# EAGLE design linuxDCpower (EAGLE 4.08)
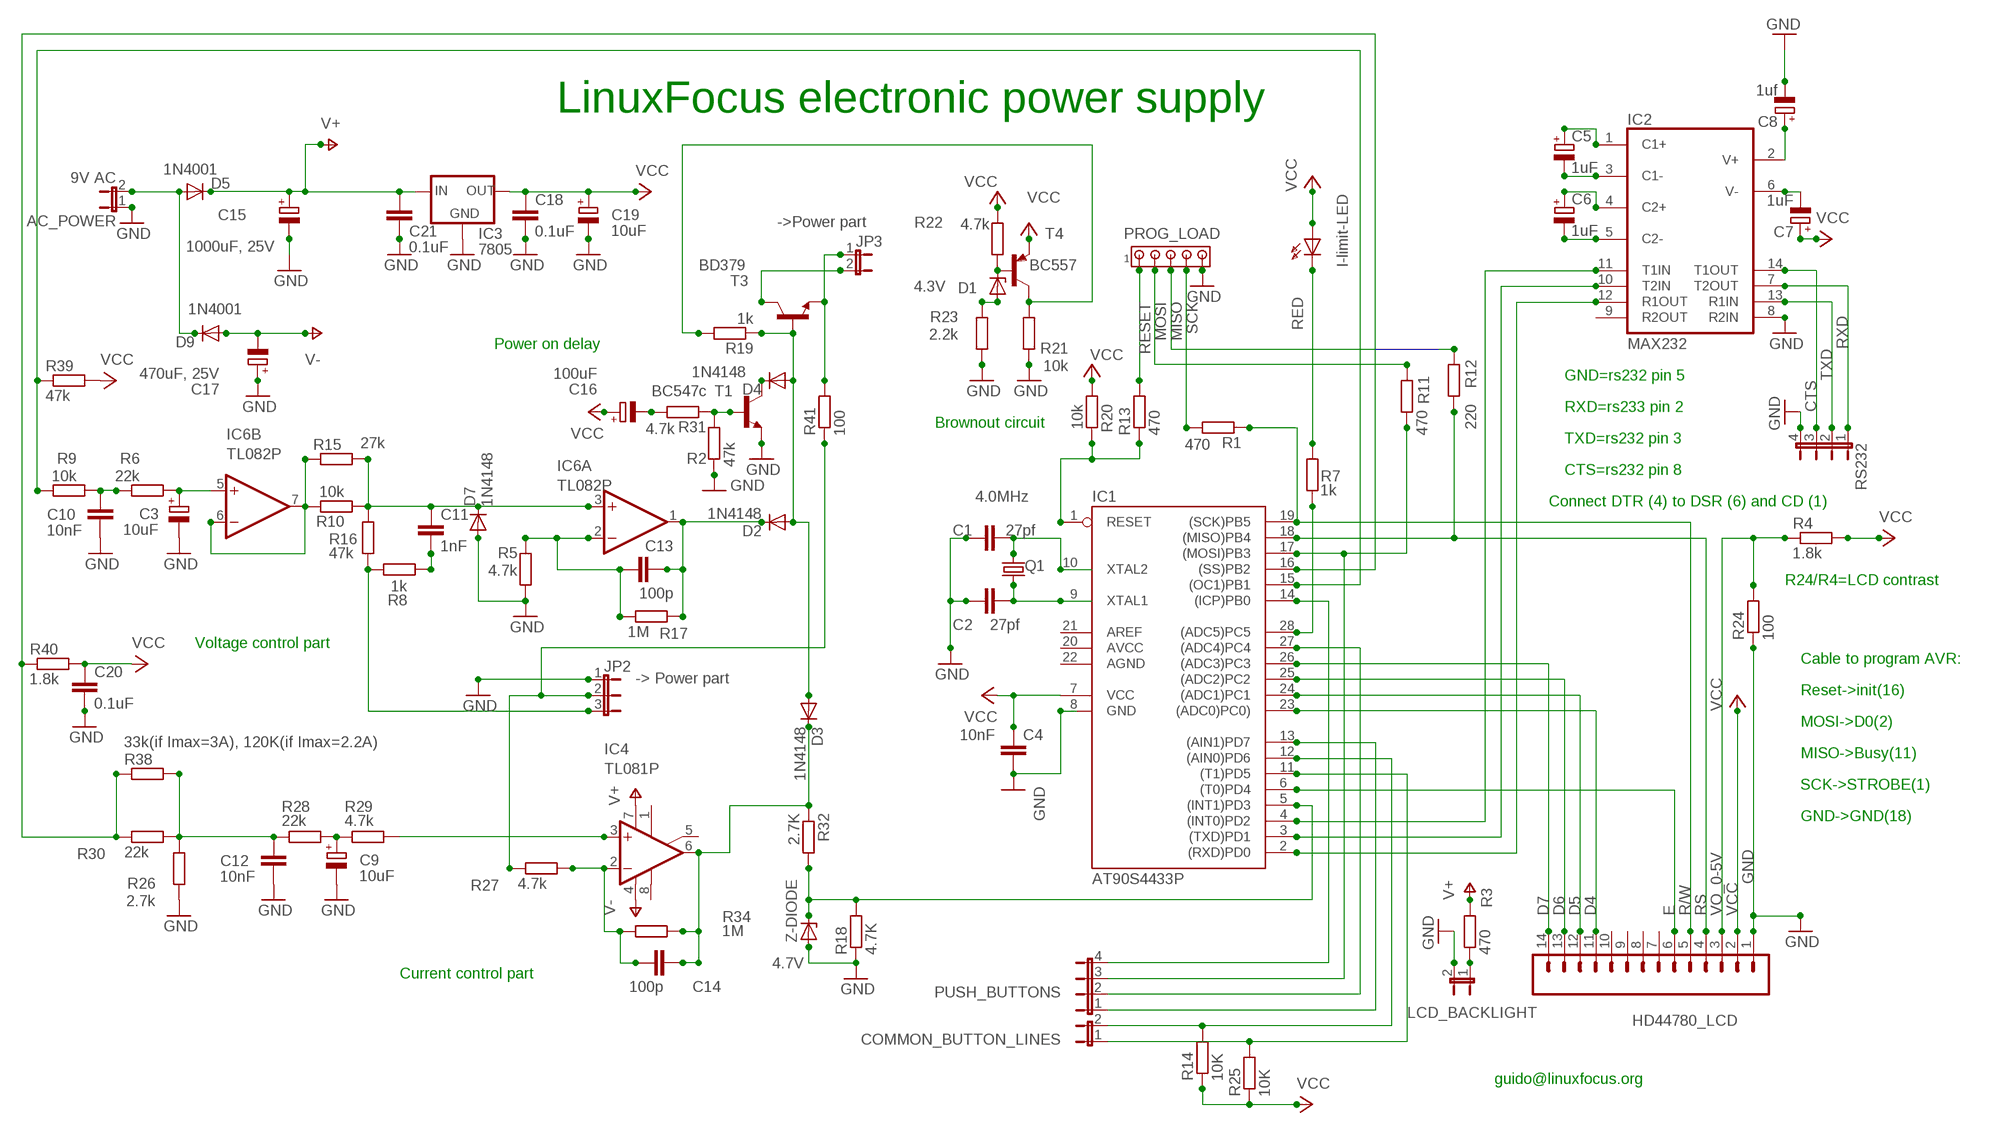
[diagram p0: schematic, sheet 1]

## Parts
AC_POWER  9V AC  JP1E  [JP1]
C1  27pf  C2.5/2  [C2.5-2]
C2  27pf  C2.5/2  [C2.5-2]
C3  10uF  CPOL-EUE2.5-6  [E2,5-6]
C4  10nF  C-EU025-030X050  [C025-030X050]
C5  1uF  CPOL-EUE2.5-6  [E2,5-6]
C6  1uF  CPOL-EUE2.5-6  [E2,5-6]
C7  1uF  CPOL-EUE2.5-6  [E2,5-6]
C8  1uf  CPOL-EUE2.5-6  [E2,5-6]
C9  10uF  CPOL-EUE2.5-6  [E2,5-6]
C10  10nF  C-EU025-030X050  [C025-030X050]
C11  1nF  C-EU025-030X050  [C025-030X050]
C12  10nF  C-EU025-030X050  [C025-030X050]
C13  100p  C-EU025-030X050  [C025-030X050]
C14  100p  C-EU025-030X050  [C025-030X050]
C15  1000uF, 25V  CPOL-EUE5-13  [E5-13]
C16  100uF  CPOL-EUE2.5-6  [E2,5-6]
C17  470uF, 25V  CPOL-EUE3.5-10  [E3,5-10]
C18  0.1uF  C-EU025-040X050  [C025-040X050]
C19  10uF  CPOL-EUE2.5-7  [E2,5-7]
C20  0.1uF  C-EU025-030X050  [C025-030X050]
C21  0.1uF  C-EU025-030X050  [C025-030X050]
COMMON_BUTTON_LINES  JP1E  [JP1]
D1  4.3V  ZENER-DIODEZD-5  [ZDIO-5]
D2  1N4148  DIODE-D-5  [D-5]
D3  1N4148  DIODE-D-5  [D-5]
D4  1N4148  DIODE-D-5  [D-5]
D5  1N4001  1N4004  [DO41-10]
D7  1N4148  DIODE-D-5  [D-5]
D9  1N4001  1N4004  [DO41-10]
HD44780_LCD  M14  [14P]
IC1  AT90S4433P  [DIL28-3]
IC2  MAX232  [DIL16]
IC3  7805  78XXS  [78XXS]
IC4  TL081P  [DIL08]
IC6  TL082P  [DIL08]
JP2  -> Power part  JP2E  [JP2]
JP3  ->Power part  JP1E  [JP1]
LCD_BACKLIGHT  JP1E  [JP1]
PROG_LOAD  MTA05-100  [10X05MTA]
PUSH_BUTTONS  JP4E  [JP4]
Q1  4.0MHz  HC49U-V  [HC49U-V]
R1  470  R-EU_0204/7  [0204/7]
R2  47k  R-EU_0204/7  [0204/7]
R3  470  R-EU_0204/5  [0204/5]
R4  1.8k  R-EU_0204/7  [0204/7]
R5  4.7k  R-EU_0204/5  [0204/5]
R6  22k  R-EU_0204/5  [0204/5]
R7  1k  R-EU_0204/7  [0204/7]
R8  1k  R-EU_0204/7  [0204/7]
R9  10k  R-EU_0204/7  [0204/7]
R10  10k  R-EU_0204/7  [0204/7]
R11  470  R-EU_0207/10  [0207/10]
R12  220  R-EU_0207/10  [0207/10]
R13  470  R-EU_0204/7  [0204/7]
R14  10K  R-EU_0207/10  [0207/10]
R15  27k  R-EU_0204/7  [0204/7]
R16  47k  R-EU_0204/7  [0204/7]
R17  1M  R-EU_0204/5  [0204/5]
R18  4.7K  R-EU_0204/7  [0204/7]
R19  1k  R-EU_0204/7  [0204/7]
R20  10k  R-EU_0204/7  [0204/7]
R21  10k  R-EU_0204/7  [0204/7]
R22  4.7k  R-EU_0204/7  [0204/7]
R23  2.2k  R-EU_0204/7  [0204/7]
R24  100  R-EU_0204/7  [0204/7]
R25  10K  R-EU_0204/7  [0204/7]
R26  2.7k  R-EU_0204/7  [0204/7]
R27  4.7k  R-EU_0204/7  [0204/7]
R28  22k  R-EU_0204/7  [0204/7]
R29  4.7k  R-EU_0204/7  [0204/7]
R30  22k  R-EU_0204/7  [0204/7]
R31  4.7k  R-EU_0204/7  [0204/7]
R32  2.7K  R-EU_0204/7  [0204/7]
R34  1M  R-EU_0204/7  [0204/7]
R38  33k(if Imax=3A), 120K(if Imax=2.2A)  R-EU_0204/7  [0204/7]
R39  47k  R-EU_0204/7  [0204/7]
R40  1.8k  R-EU_0204/7  [0204/7]
R41  100  R-EU_0204/7  [0204/7]
RED  I-limit-LED  LED3MM  [LED3MM]
RS232  JP4E  [JP4]
T1  BC547c  BC547  [TO92]
T3  BD379  BD139  [TO126]
T4  BC557  [TO92]
Z-DIODE  4.7V  ZTE  [DO35Z10]

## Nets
CTS: IC2.14(T1OUT) RS232.3
D4: HD44780_LCD.11 IC1.23((ADC0)PC0))
D5: HD44780_LCD.12 IC1.24((ADC1)PC1)
D6: HD44780_LCD.13 IC1.25((ADC2)PC2)
D7: HD44780_LCD.14 IC1.26((ADC3)PC3)
E: HD44780_LCD.6 IC1.6((T0)PD4)
GND: AC_POWER.1 C1.1 C2.1 C3.- C4.2 C8.- C9.- C10.2 C12.2 C15.- C17.+ C18.2 C19.- C20.2 C21.2 D7.A HD44780_LCD.1 IC1.8(GND) IC2.8(R2IN) IC3.GND JP2.1 LCD_BACKLIGHT.2 PROG_LOAD.5 R2.1 R5.1 R18.1 R21.1 R23.1 R24.1 R26.1 RS232.4 T1.1(E) Z-DIODE.A
MISO: PROG_LOAD.3 R12.2
MOSI: PROG_LOAD.2 R11.2
N$1: IC1.17((MOSI)PB3) PUSH_BUTTONS.3 R11.1
N$2: C2.2 IC1.9(XTAL1) Q1.1
N$3: LCD_BACKLIGHT.1 R3.1
N$4: D2.A D3.A D4.A R19.1 T3.3(B)
N$5: IC1.28((ADC5)PC5) R7.2
N$6: D4.C T1.3(C)
N$7: R7.1 RED.K(C)
N$8: C13.2 D2.C IC6.1(A:OUT) R17.2
N$9: IC6.6(B:-IN) IC6.7(B:OUT) R10.2 R15.1
N$10: C13.1 IC6.2(A:-IN) R5.2 R17.1
N$11: C3.+ IC6.5(B:+IN) R6.1
N$12: C10.1 R6.2 R9.1
N$14: C14.2 IC4.2(-IN) R27.2 R34.1
N$15: C11.1 D7.C IC6.3(A:+IN) R10.1 R15.2 R16.1
N$16: C11.2 R8.1
N$17: AC_POWER.2 D5.A D9.C
N$18: IC1.16((SS)PB2) R30.1 R38.1 R40.1
N$19: IC1.14((ICP)PB0) PUSH_BUTTONS.4
N$20: IC1.13((AIN1)PD7) PUSH_BUTTONS.1
N$21: JP3.1 R41.2 T3.1(E)
N$24: IC1.1(RESET) R13.1 R20.2
N$25: C6.- IC2.5(C2-)
N$26: C6.+ IC2.4(C2+)
N$27: C7.- IC2.6(V-)
N$28: C8.+ IC2.2(V+)
N$29: C5.- IC2.3(C1-)
N$30: C5.+ IC2.1(C1+)
N$31: IC1.3((TXD)PD1) IC2.10(T2IN)
N$32: IC1.4((INT0)PD2) IC2.11(T1IN)
N$34: IC1.2((RXD)PD0) IC2.12(R1OUT)
N$36: C1.2 IC1.10(XTAL2) Q1.2
N$37: C9.+ R28.2 R29.1
N$38: C12.1 R26.2 R28.1 R30.2 R38.2
N$39: IC4.3(+IN) R29.2
N$40: IC1.15((OC1)PB1) R9.2 R39.1
N$41: C14.1 D3.C IC4.6(OUT) R32.1 R34.2
N$42: COMMON_BUTTON_LINES.2 IC1.12((AIN0)PD6) R14.2
N$43: JP3.2 T3.2(C)
N$44: R2.2 R31.1 T1.2(B)
N$45: COMMON_BUTTON_LINES.1 IC1.11((T1)PD5) R25.2
N$47: D1.A R23.2
N$48: D1.C R22.1 T4.2(B)
N$49: IC1.5((INT1)PD3) R18.2 R32.2 Z-DIODE.C
N$50: IC1.27((ADC4)PC4) PUSH_BUTTONS.2
N$51: C16.- R31.2
N$53: R19.2 R21.2 T4.3(C)
N$54: JP2.2 R27.1 R41.1
N$57: JP2.3 R8.2 R16.2
R/W: HD44780_LCD.5 IC1.19((SCK)PB5) R1.1
RESET: PROG_LOAD.1 R13.2
RS: HD44780_LCD.4 IC1.18((MISO)PB4) R12.1
RXD: IC2.7(T2OUT) RS232.1
SCK: PROG_LOAD.4 R1.2
TXD: IC2.13(R1IN) RS232.2
V+: C15.+ C21.1 D5.C IC3.IN IC4.7(V+) R3.2
V-: C17.- D9.A IC4.4(V-)
VCC: C4.1 C7.+ C16.+ C18.1 C19.+ C20.1 HD44780_LCD.2 IC1.7(VCC) IC3.OUT R4.2 R14.1 R20.1 R22.2 R25.1 R39.2 R40.2 RED.A T4.1(E)
VO_0-5V: HD44780_LCD.3 R4.1 R24.2
Unconnected: HD44780_LCD.7 HD44780_LCD.8 HD44780_LCD.9 HD44780_LCD.10 IC2.9(R2OUT) IC4.1(ON1) IC4.5(ON2) IC4.8(OPT)

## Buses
B$1

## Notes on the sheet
- LinuxFocus electronic power supply
- Power on delay
- GND=rs232 pin 5
- RXD=rs233 pin 2
- Brownout circuit
- TXD=rs232 pin 3
- CTS=rs232 pin 8
- Connect DTR (4) to DSR (6) and CD (1)
- R24/R4=LCD contrast
- Voltage control part
- Cable to program AVR:
- Reset->init(16)
- MOSI->D0(2)
- MISO->Busy(11)
- SCK->STROBE(1)
- GND->GND(18)
- Current control part
- guido@linuxfocus.org

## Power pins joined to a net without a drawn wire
AGND: IC1.22(AGND)
AREF: IC1.21(AREF)
AVCC: IC1.20(AVCC)
GND: IC2.15(GND)
V+: IC6.8(P:V+)
V-: IC6.4(P:V-)
VCC: IC2.16(VCC)

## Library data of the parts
AC_POWER COMMON_BUTTON_LINES JP3 LCD_BACKLIGHT = jumper:JP1E: JUMPER
C1 C2 = capacitor-wima:C: CAPACITOR
C3 C5-C9 C15-C17 C19 = rcl:CPOL-EU: POLARIZED CAPACITOR, European symbol
C4 C10-C14 C18 C20 C21 = rcl:C-EU: CAPACITOR, European symbol
D1 = diode:ZENER-DIODE: Z-Diode
D2-D4 D7 = diode:DIODE-: DIODE
D5 D9 = diode:1N4004: DIODE
HD44780_LCD = con-amp-quick:M14: AMP QUICK CONNECTOR
IC1 = atmel:AT90S4433: MICROCONTROLLER 4 Kbytes FLASH 128 bytes SRAM 256 bytes EEPROM UART 6-channel 10 bit ADC
IC2 = maxim:MAX232: RS232 TRANSEIVER
IC3 = v-reg:78XXS: VOLTAGE REGULATOR
IC4 = linear:TL081: OP AMP
IC6 = linear:TL082: OP AMP
JP2 = jumper:JP2E: JUMPER
PROG_LOAD = con-amp:MTA05-100: AMP CONNECTOR
PUSH_BUTTONS RS232 = jumper:JP4E: JUMPER
Q1 = crystal:HC49U-V: CRYSTAL
R1-R3 R5-R19 R24-R32 R34 R38-R41 = rcl:R-EU_: RESISTOR, European symbol
R4 R20-R23 = rcl_gus:R-EU_: RESISTOR, European symbol
RED = led:LED3MM: LED
T1 = transistor-npn:BC547: NPN TRANSISTOR
T3 = transistor-npn:BD139: NPN TRANSISTOR
T4 = transistor-pnp:BC557: PNP TRANSISTOR
Z-DIODE = diode:ZTE: Z DIODE

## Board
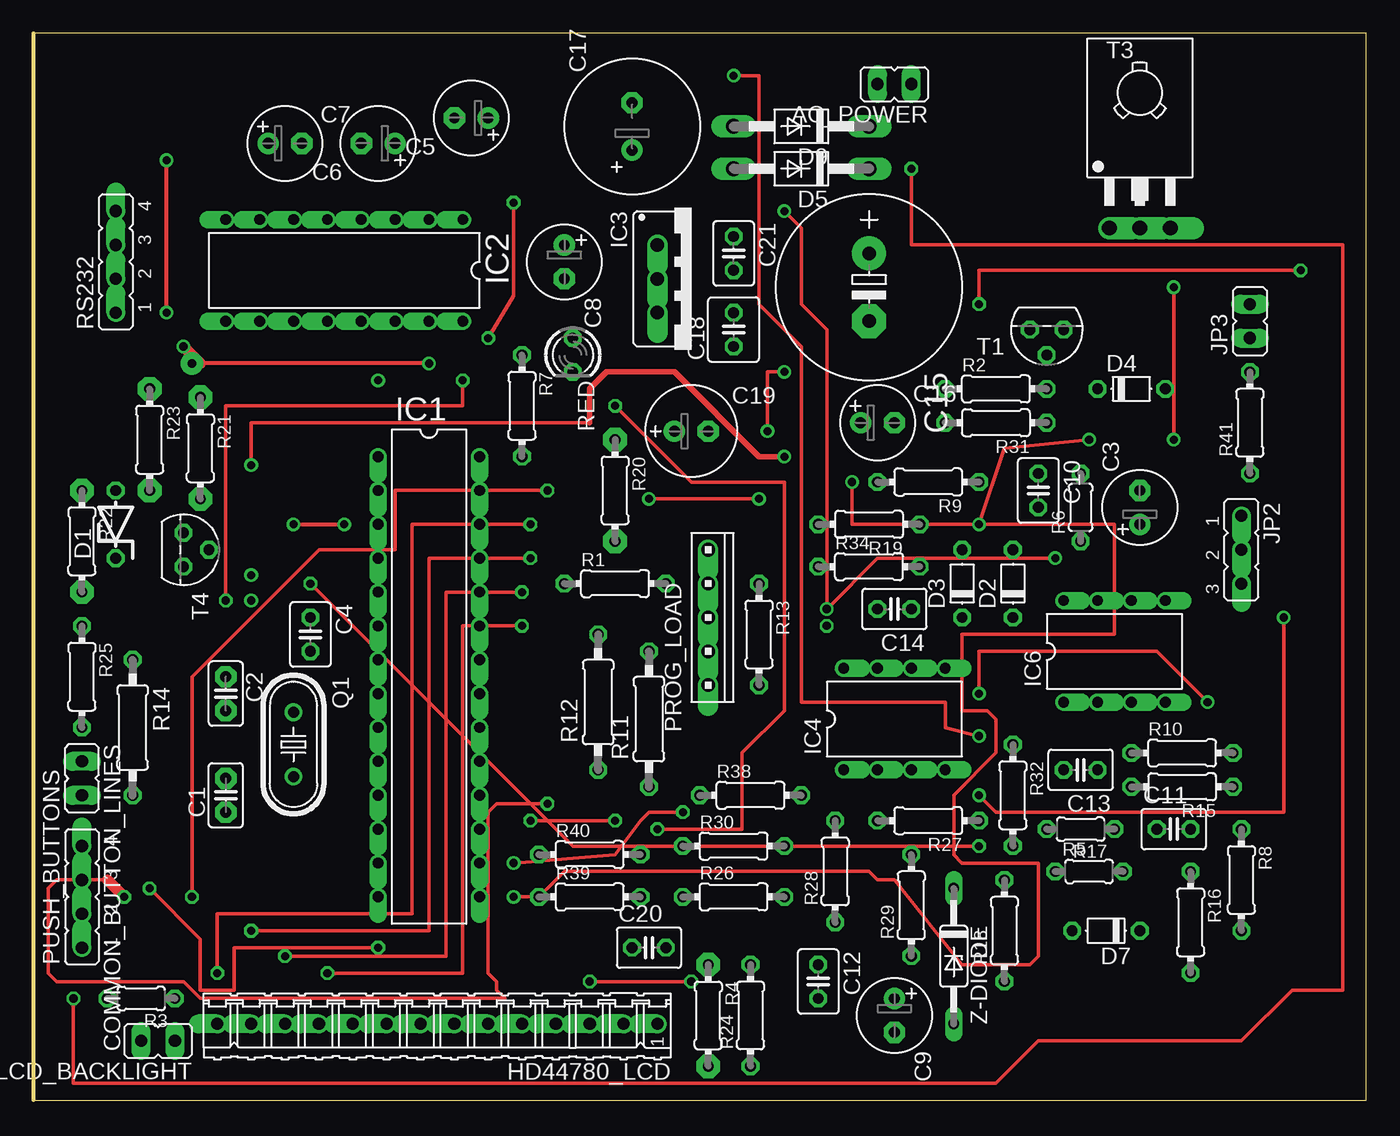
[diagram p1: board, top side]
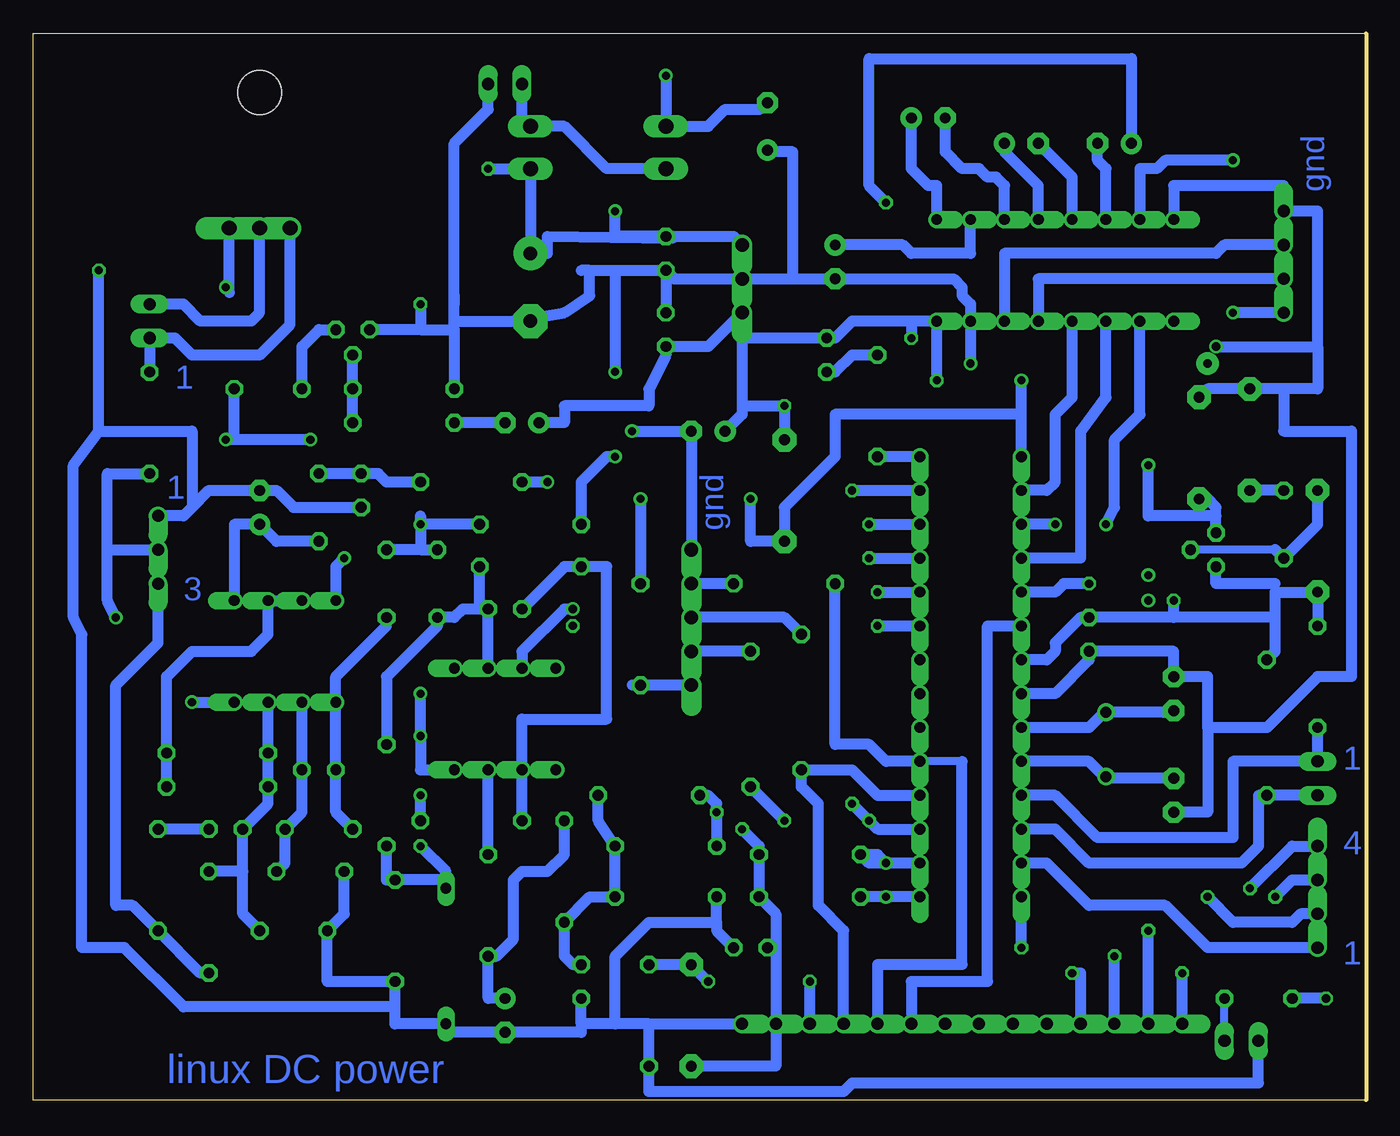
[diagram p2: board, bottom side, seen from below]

Size 100 x 80 mm. Coordinates in mm from the lower left corner, seen from the top.
Outline: 0,0 100,0 100,80 0,80 0,0
Copper layers used: Top, Bottom

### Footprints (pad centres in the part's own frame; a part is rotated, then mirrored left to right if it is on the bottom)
JP1 = drill 0.914 long: 1 0,-1.27; 2 0,1.27
C2.5-2 = drill 0.813 pad 1.6 octagon: 1 -1.27,0; 2 1.27,0
E2,5-6 = drill 0.813 pad 1.6 round: + -1.27,0 | drill 0.813 pad 1.6 octagon: - 1.27,0
C025-030X050 = drill 0.813 octagon: 1 -1.27,0; 2 1.27,0
E5-13 = drill 1.016 pad 2.54 round: + -2.54,0 | drill 1.016 pad 2.54 octagon: - 2.54,0
E3,5-10 = drill 0.813 pad 1.6 round: + -1.778,0 | drill 0.813 pad 1.6 octagon: - 1.778,0
C025-040X050 = drill 0.813 octagon: 1 -1.27,0; 2 1.27,0
E2,5-7 = drill 0.813 pad 1.6 round: + -1.27,0 | drill 0.813 pad 1.6 octagon: - 1.27,0
ZDIO-5 = drill 0.813 octagon: A 2.54,0; C -2.54,0
D-5 = drill 0.813 octagon: A 2.54,0; C -2.54,0
DO41-10 = drill 1.118 long: A 5.08,0; C -5.08,0
14P = drill 0.914 offset: 1 -16.51,0; 2 -13.97,0; 3 -11.43,0; 4 -8.89,0; 5 -6.35,0; 6 -3.81,0; 7 -1.27,0; 8 1.27,0; 9 3.81,0; 10 6.35,0; 11 8.89,0; 12 11.43,0; 13 13.97,0; 14 16.51,0
DIL28-3 = drill 0.813 offset: 1 -16.51,-3.81; 2 -13.97,-3.81; 3 -11.43,-3.81; 4 -8.89,-3.81; 5 -6.35,-3.81; 6 -3.81,-3.81; 7 -1.27,-3.81; 8 1.27,-3.81; 9 3.81,-3.81; 10 6.35,-3.81; 11 8.89,-3.81; 12 11.43,-3.81; 13 13.97,-3.81; 14 16.51,-3.81; 15 16.51,3.81; 16 13.97,3.81; 17 11.43,3.81; 18 8.89,3.81; 19 6.35,3.81; 20 3.81,3.81; 21 1.27,3.81; 22 -1.27,3.81; 23 -3.81,3.81; 24 -6.35,3.81; 25 -8.89,3.81; 26 -11.43,3.81; 27 -13.97,3.81; 28 -16.51,3.81
DIL16 = drill 0.813 offset: 1 -8.89,-3.81; 2 -6.35,-3.81; 3 -3.81,-3.81; 4 -1.27,-3.81; 5 1.27,-3.81; 6 3.81,-3.81; 7 6.35,-3.81; 8 8.89,-3.81; 9 8.89,3.81; 10 6.35,3.81; 11 3.81,3.81; 12 1.27,3.81; 13 -1.27,3.81; 14 -3.81,3.81; 15 -6.35,3.81; 16 -8.89,3.81
78XXS = drill 1.016 offset: GND 0,-2.54; IN -2.54,-2.54; OUT 2.54,-2.54
DIL08 = drill 0.813 offset: 1 -3.81,-3.81; 2 -1.27,-3.81; 3 1.27,-3.81; 4 3.81,-3.81; 5 3.81,3.81; 6 1.27,3.81; 7 -1.27,3.81; 8 -3.81,3.81
JP2 = drill 0.914 offset: 1 -2.54,0; 2 0,0; 3 2.54,0
10X05MTA = drill 1.016 offset: 1 5.08,0; 2 2.54,0; 3 0,0; 4 -2.54,0; 5 -5.08,0
JP4 = drill 0.914 offset: 1 -3.81,0; 2 -1.27,0; 3 1.27,0; 4 3.81,0
HC49U-V = drill 0.813 round: 1 -2.413,0; 2 2.413,0
0204/7 = drill 0.813 octagon: 1 -3.81,0; 2 3.81,0
0204/5 = drill 0.813 octagon: 1 -2.54,0; 2 2.54,0
0204/7' = drill 0.813 pad 1.778 octagon: 1 -3.81,0; 2 3.81,0
0207/10 = drill 0.813 octagon: 1 -5.08,0; 2 5.08,0
LED3MM = drill 0.813 octagon: A -1.27,0; K 1.27,0
TO92 = drill 0.813 octagon: 1 1.27,0; 2 0,1.905; 3 -1.27,0
TO126 = drill 1.118 offset: 1 -2.286,-5.08; 2 0,-5.08; 3 2.286,-5.08 | hole 3.302: 0,5.08
DO35Z10 = drill 0.813 long: A 5.08,0; C -5.08,0

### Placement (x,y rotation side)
AC_POWER  64.61,76.19 90 top
C1  14.44,22.86 90 top
C2  14.44,30.47 270 top
C3  83.02,44.45 90 top
C4  20.79,34.92 270 top
C5  32.85,73.66 180 top
C6  25.87,71.75 180 top
C7  18.88,71.75 0 top
C8  39.84,62.86 270 top
C9  64.61,6.34 270 top
C10  75.4,45.72 270 top
C11  85.56,20.31 0 top
C12  58.89,8.89 270 top
C13  78.58,24.76 180 top
C14  64.61,36.83 180 top
C15  62.7,60.96 270 top
C16  63.34,50.8 0 top
C17  44.92,73.02 90 top
C18  52.54,57.78 90 top
C19  49.37,50.16 0 top
C20  46.19,11.43 0 top
C21  52.54,63.5 270 top
COMMON_BUTTON_LINES  3.64,24.12 180 top
D1  6.18,43.18 90 top
D2  73.5,38.73 90 top
D3  69.69,38.73 90 top
D4  82.39,53.34 0 top
D5  57.62,69.84 180 top
D7  80.48,12.7 180 top
D9  57.62,73.02 180 top
HD44780_LCD  30.31,5.71 180 top
IC1  29.68,31.74 270 top
IC2  23.33,62.23 180 top
IC3  49.37,61.59 270 top
IC4  64.61,28.57 0 top
IC6  81.11,33.65 0 top
JP2  90.64,41.27 270 top
JP3  91.28,58.41 0 top
LCD_BACKLIGHT  9.36,4.44 90 top
PROG_LOAD  50.63,36.19 270 top
PUSH_BUTTONS  3.64,15.24 90 top
Q1  19.52,26.66 270 top
R1  43.65,38.73 0 top
R2  72.22,53.34 0 top
R3  8.09,7.62 180 top
R4  1.8k  [0204/7']  50.63,6.34 270 top
R5  79.21,17.14 0 top
R6  78.58,44.45 90 top
R7  36.66,52.07 270 top
R8  90.64,16.5 270 top
R9  67.14,46.35 180 top
R10  86.19,26.03 0 top
R11  46.19,28.57 90 top
R12  42.38,29.84 90 top
R13  54.45,34.92 270 top
R14  7.46,27.93 270 top
R15  86.19,23.49 180 top
R16  86.83,13.33 270 top
R17  78.58,20.31 180 top
R18  72.86,12.7 90 top
R19  62.7,43.18 180 top
R20  10k  [0204/7']  43.65,45.72 270 top
R21  10k  [0204/7']  12.54,48.89 270 top
R22  4.7k  [0204/7']  3.64,41.91 270 top
R23  2.2k  [0204/7']  8.73,49.53 270 top
R24  53.81,6.34 90 top
R25  3.64,31.74 270 top
R26  52.54,15.24 0 top
R27  67.14,20.95 180 top
R28  60.16,17.14 90 top
R29  65.88,14.6 90 top
R30  52.54,19.04 0 top
R31  72.22,50.8 180 top
R32  73.5,22.86 270 top
R34  62.7,40 0 top
R38  53.81,22.86 0 top
R39  41.74,15.24 0 top
R40  41.74,18.41 0 top
R41  91.28,50.8 90 top
RED  40.48,55.88 270 top
RS232  6.18,62.86 90 top
T1  76.03,57.78 180 top
T3  83.02,70.48 0 top
T4  11.27,41.27 270 top
Z-DIODE  69.05,10.79 270 top

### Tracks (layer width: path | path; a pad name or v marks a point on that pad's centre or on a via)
CTS
  Bottom 0.813: IC2.14 27.14,63.5 11.27,63.5 10.63,64.13 RS232.3
D4  (via drill 0.61)
  Top 0.254: v36.66,35.55 32.22,35.55 32.22,9.52 v22.06,9.52
  Bottom 0.813: v36.66,35.55 IC1.23 | v22.06,9.52 21.42,9.52 HD44780_LCD.11
D5  (via drill 0.61)
  Top 0.254: v36.66,38.1 30.95,38.1 30.95,10.79 v18.88,10.79
  Bottom 0.813: v36.66,38.1 IC1.24 | HD44780_LCD.12 v18.88,10.79
D6  (via drill 0.61)
  Top 0.254: v37.3,40.64 29.68,40.64 29.68,12.7 v16.34,12.7
  Bottom 0.813: v37.3,40.64 IC1.25 | HD44780_LCD.13 v16.34,12.7
D7  (via drill 0.61)
  Top 0.254: v13.81,9.52 13.81,13.97 28.41,13.97 28.41,43.18 v37.3,43.18
  Bottom 0.813: HD44780_LCD.14 v13.81,9.52 | v37.3,43.18 IC1.26
E
  Bottom 0.813: HD44780_LCD.6 34.12,8.89 28.41,8.89 28.41,35.55 IC1.6
GND  (via drill 0.61)
  Top 0.254: v55.08,50.16 55.08,54.61 v56.35,54.61 | v95.08,62.23 70.95,62.23 v70.95,59.69
  Top 0.305: v29.68,55.24 12.54,55.24
  Top 0.813: 12.54,55.24 v11.27,56.51
  Bottom 0.813: IC1.8 23.33,30.47 20.79,33.02 C4.2 14.44,33.65 C2.1 11.9,31.74 11.9,27.93 | 11.9,53.34 R23.1 6.18,53.34 | IC2.8 14.44,68.57 6.18,68.57 RS232.4 3.64,66.67 3.64,56.51 | 3.64,56.51 3.64,53.34 6.18,53.34 | 29.68,59.69 IC2.15 | 29.68,59.69 30.31,60.32 30.31,60.96 30.95,61.59 C8.- 43.02,61.59 | 29.68,59.69 v29.68,55.24 | v11.27,56.51 3.64,56.51 | 11.9,53.34 R21.1 | 6.18,53.34 11.9,53.34 | 6.18,53.34 6.18,50.16 1.1,50.16 1.1,31.74 3.64,31.74 7.46,27.93 11.9,27.93 | 68.41,60.32 68.41,59.69 | 68.41,58.41 63.97,58.41 | AC_POWER.1 65.88,74.29 68.41,71.75 68.41,60.32 | 43.02,61.59 43.02,71.11 44.92,71.11 C17.+ | 43.02,61.59 IC3.GND 51.91,61.59 C21.2 | C21.2 C18.2 | C10.2 80.48,44.45 81.75,45.72 C3.- 86.83,45.72 88.1,44.45 | R5.1 76.67,13.97 D7.A 77.94,8.89 R18.1 72.86,6.98 | 88.1,44.45 88.73,43.81 JP2.1 | 53.81,5.71 R24.1 53.81,0.63 39.2,0.63 38.57,1.27 8.09,1.27 LCD_BACKLIGHT.2 | 58.89,5.71 C12.2 | 58.89,5.08 C9.- 69.05,5.08 | 70.95,57.78 68.41,57.78 | 70.95,57.78 T1.1 | 68.41,57.78 R2.1 | 68.41,57.78 68.41,58.41 | 68.41,58.41 68.41,60.32 | 56.35,62.23 C21.2 | 58.25,62.23 56.35,62.23 | 58.25,62.23 58.25,60.32 60.16,59.05 63.97,58.41 | 58.25,62.23 58.89,62.23 | 63.97,58.41 C15.- | v55.08,50.16 C19.- PROG_LOAD.5 | 56.35,62.23 v56.35,54.61 | 56.35,5.71 58.89,5.71 | 53.81,5.71 56.35,5.71 | 53.81,5.71 HD44780_LCD.1 | 58.89,5.71 58.89,5.08 | 58.89,5.08 69.05,5.08 | 69.05,5.08 Z-DIODE.A 72.86,5.71 72.86,6.98 | 72.86,6.98 88.73,6.98 93.18,11.43 96.36,11.43 96.36,34.92 96.99,36.19 96.99,47.62 95.08,50.16 | 95.08,50.16 v95.08,62.23 | v70.95,59.69 70.95,57.78 | 95.08,50.16 88.1,50.16 88.1,44.45 | 48.73,13.33 R26.1 | 48.73,13.33 53.81,13.33 56.35,10.79 56.35,5.71
  Bottom 0.813: C1.1 11.9,21.58 11.9,27.93 | 48.73,13.33 48.73,12.7 C20.2
MISO
  Bottom 0.813: PROG_LOAD.3 43.65,36.19 R12.2
MOSI
  Bottom 0.813: R11.2 PROG_LOAD.2
N$1  (via drill 0.61)
  Top 0.254: v37.3,20.95 v43.65,20.95 | v38.57,22.22 34.76,22.22 34.12,21.58 34.12,9.52 34.76,8.89 34.76,8.25 35.39,7.62 12.54,7.62 11.27,8.89 1.74,8.89 1.1,9.52 1.1,15.87 1.74,16.5 5.55,16.5
  Top 0.813: 5.55,16.5 v6.82,15.24
  Bottom 0.813: 36.66,20.31 v37.3,20.95 | v43.65,20.95 R11.1 | 36.66,20.31 IC1.17 | v38.57,22.22 36.66,20.31 | v6.82,15.24 5.55,16.5 PUSH_BUTTONS.3
N$2
  Bottom 0.813: IC1.9 20.79,27.93 19.52,29.2 Q1.1 15.2,29.08 C2.2
N$3
  Bottom 0.61: LCD_BACKLIGHT.1 R3.1
N$4  (via drill 0.61)
  Top 0.254: v85.56,49.53 v85.56,60.96 | v79.21,49.53 72.86,48.89 v70.95,43.18
  Bottom 0.813: 70.95,41.27 D3.A | 70.95,41.27 D2.A | T3.3 85.31,60.57 v85.56,60.96 | 84.92,49.53 v85.56,49.53 | 84.92,49.53 D4.A | v79.21,49.53 84.92,49.53 | 70.95,41.27 70.95,43.81 v70.95,43.18 R19.1
N$5
  Bottom 0.813: IC1.28 R7.2
N$6
  Bottom 0.813: T1.3 78.58,57.78 79.84,56.51 D4.C
N$7
  Bottom 0.813: R7.1 38.57,55.88 39.84,54.61 RED.K
N$8
  Bottom 0.813: R17.2 77.3,21.58 C13.2 IC6.1 77.3,31.74 73.5,35.55 D2.C
N$9
  Bottom 0.813: IC6.7 IC6.6 82.39,34.92 83.66,33.65 88.1,33.65 90,31.74 R10.2 R15.1
N$10
  Bottom 0.813: IC6.2 C13.1 79.84,21.58 R17.1 81.11,17.77 R5.2
N$11
  Bottom 0.813: R6.1 81.75,41.91 C3.+ 84.92,43.18 IC6.5
N$12
  Bottom 0.813: R9.1 73.5,46.35 74.13,46.98 C10.1 R6.2
N$14
  Bottom 0.813: R27.2 IC4.2 63.34,28.57 56.98,28.57 56.98,40 R34.1 60.16,40 C14.2
N$15
  Bottom 0.813: IC6.3 R10.1 R15.2 82.39,22.22 C11.1 84.29,17.14 | 84.29,17.14 R16.1 | 84.29,17.14 84.29,13.97 D7.C
N$16
  Bottom 0.813: C11.2 R8.1
N$17
  Bottom 0.813: AC_POWER.2 63.34,73.66 D9.C 60.16,73.02 56.98,69.84 D5.A
N$18  (via drill 0.61)
  Top 0.254: v36.03,17.77 43.65,18.41 45.55,20.95 46.19,21.58 v48.73,21.58
  Bottom 0.813: IC1.16 v36.03,17.77 | v36.03,17.77 37.3,17.77 R40.1 36.66,18.41 v36.03,17.77 | R38.1 49.37,22.86 48.73,22.22 v48.73,21.58 R30.1
N$19  (via drill 0.61)
  Top 0.254: v25.87,11.43 15.08,11.43 15.08,8.25 12.54,8.25 12.54,12.06 v8.73,15.87
  Bottom 0.813: PUSH_BUTTONS.4 5.55,19.04 v8.73,15.87 | v25.87,11.43 IC1.14
N$20
  Bottom 0.813: IC1.13 23.96,17.77 20.79,14.6 15.08,14.6 11.9,11.43 PUSH_BUTTONS.1
N$21
  Bottom 0.813: T3.1 80.73,58.16 83.02,55.88 88.1,55.88 89.37,57.15 JP3.1 R41.2
N$24  (via drill 0.61)
  Top 0.254: v46.19,45.08 v54.45,45.08
  Bottom 0.813: 25.87,51.43 v25.87,53.97 | IC1.1 25.87,51.43 | 25.87,51.43 39.84,51.43 39.84,48.26 43.65,44.45 R20.2 46.19,41.91 v46.19,45.08 | v54.45,45.08 R13.1
N$25
  Bottom 0.813: IC2.5 22.06,69.21 C6.-
N$26
  Bottom 0.813: C6.+ 27.14,71.11 24.6,68.57 IC2.4
N$27
  Bottom 0.813: C7.- 20.15,70.48 19.52,69.84 IC2.6
N$28
  Bottom 0.813: IC2.2 29.68,63.5 34.12,63.5 34.76,64.13 C8.+
N$29
  Bottom 0.813: C5.- 31.58,71.11 30.31,69.84 29.04,69.84 28.41,69.21 27.77,69.21 27.14,68.57 IC2.3
N$30
  Bottom 0.813: IC2.1 32.22,68.57 32.85,68.57 34.12,69.84 C5.+
N$31  (via drill 0.61)
  Top 0.305: v19.52,43.18 v23.33,43.18
  Bottom 0.813: IC2.10 16.98,51.43 18.88,49.53 18.88,44.45 v19.52,43.18 | v23.33,43.18 IC1.3
N$32
  Bottom 0.813: IC1.4 21.42,40.64 21.42,50.16 19.52,52.7 IC2.11
N$34
  Bottom 0.813: IC2.12 22.06,52.7 23.33,51.43 23.33,46.35 23.96,45.72 IC1.2
N$35  (via drill 0.61 pad 1.68)
  other vias: 11.9,55.24
N$36
  Bottom 0.813: IC1.10 20.79,25.39 19.52,24.12 | 19.52,24.12 Q1.2 | C1.2 19.52,24.12
N$37
  Bottom 0.813: R28.2 60.16,18.41 61.43,17.14 63.34,17.14 63.97,16.5 63.97,12.06 65.24,10.79 R29.1 65.88,7.62 C9.+
N$38
  Bottom 0.813: R38.2 57.62,20.95 R30.2 R26.2 58.25,15.24 R28.1 60.16,10.79 59.52,10.16 C12.1
N$39
  Bottom 0.813: R29.2 IC4.3
N$40  (via drill 0.61)
  Top 0.254: v36.03,15.24 R39.1 39.84,17.14 62.7,17.14 63.34,16.5 64.61,16.5 69.69,10.16 74.77,10.16 75.4,10.79 75.4,17.77 69.69,17.77 69.05,18.41 69.05,22.86 72.22,26.03 72.22,28.57 71.59,29.2 69.69,29.2 69.69,34.92 81.11,34.92 81.11,43.18 61.43,43.18 v61.43,46.35
  Bottom 0.813: IC1.15 v36.03,15.24 R39.1 | v61.43,46.35 R9.2
N$41
  Bottom 0.813: R34.2 66.51,36.83 C14.1 | IC4.6 C14.1 | C14.1 67.78,36.83 68.41,36.19 D3.C 69.69,35.55 73.5,31.74 R32.1
N$42
  Bottom 0.813: IC1.12 23.33,20.31 20.79,17.77 9.36,17.77 8.09,19.04 8.09,22.86 R14.2 COMMON_BUTTON_LINES.2
N$43
  Bottom 0.813: T3.2 83.02,59.05 83.66,58.41 87.47,58.41 88.73,59.69 JP3.2
N$44
  Bottom 0.813: T1.2 R2.2 R31.1
N$45
  Bottom 0.813: R25.2 COMMON_BUTTON_LINES.1 10,25.39 10,19.68 20.15,19.68 23.33,22.86 IC1.11
N$46  (via drill 0.61)
  other vias: 16.34,37.46
N$47
  Bottom 0.813: D1.A R23.2
N$48
  Bottom 0.61: 6.82,41.27 T4.2
  Bottom 0.813: 6.82,41.27 D1.C 3.64,43.18 R22.1
N$49  (via drill 0.61)
  Top 0.254: v70.95,19.04 40.48,19.04 v20.79,38.73
  Bottom 0.254: 69.05,17.14 69.05,16.5
  Bottom 0.813: R32.2 73.5,16.5 R18.2 69.05,16.5 Z-DIODE.C | v70.95,19.04 69.05,17.14 | v20.79,38.73 22.7,38.73 23.33,38.1 IC1.5
N$50  (via drill 0.61)
  Top 0.254: v11.9,15.24 11.9,31.74 21.42,41.27 27.14,41.27 27.14,45.72 v38.57,45.72
  Bottom 0.813: PUSH_BUTTONS.2 4.92,13.97 5.55,13.33 10,13.33 v11.9,15.24 | v38.57,45.72 IC1.27
N$51
  Bottom 0.813: C16.- R31.2
N$52  (via drill 0.61)
  other vias: 59.52,35.55
N$53  (via drill 0.61)
  Top 0.254: 41.74,50.8 16.34,50.8 v16.34,47.62
  Top 0.406: 41.74,50.8 41.74,53.34 43.02,54.61 48.09,54.61 54.45,48.26 v56.35,48.26
  Bottom 0.813: R21.2 11.9,45.08 11.27,44.45 11.27,43.81 | T4.3 11.27,43.81 | 11.27,43.81 16.34,43.81 v16.34,47.62 | v56.35,48.26 56.98,48.26 58.89,46.35 R19.2
N$54  (via drill 0.61)
  Top 0.254: v93.81,36.19 93.81,21.58 72.22,21.58 v70.95,22.86
  Bottom 0.813: R41.1 94.45,46.98 94.45,41.27 | 94.45,41.27 JP2.2 | 94.45,41.27 94.45,37.46 v93.81,36.19 | R27.1 v70.95,22.86
N$55  (via drill 0.61)
  other vias: 16.34,39.37
N$57
  Bottom 0.813: R16.2 87.47,9.52 R8.2 92.55,14.6 93.81,14.6 93.81,31.11 90.64,34.29 JP2.3
R/W
  Bottom 0.61: 30.31,25.39 IC1.19
  Bottom 0.813: IC1.19 36.03,25.39 37.3,26.66 39.84,26.66 R1.1 | 30.31,25.39 30.31,10.16 36.66,10.16 HD44780_LCD.5
RESET
  Bottom 0.813: 55.08,31.11 R13.2 PROG_LOAD.1
RS
  Bottom 0.813: IC1.18 36.66,22.86 38.57,24.76 R12.1 42.38,23.49 41.11,22.22 41.11,14.6 39.2,12.7 HD44780_LCD.4
RXD  (via drill 0.61)
  Top 0.305: v10,59.05 v10,70.48
  Bottom 0.813: IC2.7 16.98,69.84 15.71,69.84 15.08,70.48 v10,70.48 | RS232.1 v10,59.05
SCK
  Bottom 0.813: R1.2 PROG_LOAD.4
TXD
  Bottom 0.813: IC2.13 24.6,61.59 RS232.2
V+  (via drill 0.61)
  Top 0.254: v76.67,40.64 63.34,40.64 v59.52,36.83 59.52,57.78 57.62,59.69 57.62,65.4 v56.35,66.67 | v3.01,7.62 3.01,1.27 72.22,1.27 75.4,4.44 90.64,4.44 94.45,8.25 98.26,8.25 98.26,64.13 65.88,64.13 v65.88,69.84
  Bottom 0.813: C21.1 52.03,64.64 61.43,64.77 61.43,63.5 C15.+ D5.C v65.88,69.84 | C21.1 47.46,64.77 IC3.IN | IC6.8 77.3,40 v76.67,40.64 | IC4.7 63.34,33.65 60.16,36.83 v59.52,36.83 | v56.35,66.67 56.35,64.77 C21.1 | v3.01,7.62 R3.2
V-  (via drill 0.61)
  Top 0.254: v70.95,30.47 70.95,33.65 84.29,33.65 v88.1,29.84 | v52.54,76.83 54.45,76.83 54.45,59.69 57.62,56.51 57.62,29.84 68.41,29.84 68.41,27.93 v70.95,27.3
  Bottom 0.813: v88.1,29.84 IC6.4 | v52.54,76.83 D9.A 49.37,73.02 48.09,74.29 45.55,74.29 44.92,74.92 C17.- | v70.95,30.47 v70.95,27.3 70.95,24.76 IC4.4
VCC  (via drill 0.61)
  Top 0.254: v43.65,52.07 49.37,46.35 56.35,46.35 56.35,29.2 53.17,26.03 53.17,20.31 v46.82,20.31 | v36.03,67.3 36.03,60.32 v34.12,57.15 | v32.22,53.97 32.22,52.07 14.44,52.07 v14.44,37.46
  Bottom 0.406: 6.82,36.83 6.82,38.1 6.82,38.73
  Bottom 0.813: IC1.7 23.96,33.02 23.33,33.65 23.33,34.29 21.42,36.19 C4.1 14.44,36.19 | 6.82,38.73 11.27,38.73 T4.1 | 46.82,52.07 46.82,51.43 C19.+ | 46.82,57.15 46.82,52.07 | 46.82,57.15 IC3.OUT 49.37,56.51 C18.1 52.54,55.88 53.81,53.34 53.81,52.07 60.16,52.07 60.16,50.8 C16.+ | R4.2 44.28,2.54 HD44780_LCD.2 44.28,11.43 | 44.28,11.43 44.28,13.97 R39.2 R40.2 45.55,19.04 v46.82,20.31 | 46.82,52.07 v43.65,52.07 R20.1 | 46.82,57.15 RED.A 39.84,57.15 38.57,58.41 34.12,58.41 | 34.12,58.41 IC2.16 v32.22,53.97 | C7.+ 17.61,78.1 37.3,78.1 37.3,68.57 v36.03,67.3 | 34.12,58.41 v34.12,57.15 | R25.1 R22.2 6.82,38.1 6.82,36.19 | 6.82,36.19 6.82,33.65 R14.1 | 6.82,36.19 14.44,36.19 | 14.44,36.19 v14.44,37.46 | 44.28,11.43 C20.1
VO_0-5V  (via drill 0.61)
  Top 0.254: v41.74,8.89 v49.37,8.89
  Bottom 0.813: R24.2 R4.1 v49.37,8.89 | HD44780_LCD.3 v41.74,8.89

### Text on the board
Bottom: gnd | 1 | gnd | 1 | 3 | 1 | 4 | 1 | linux DC power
